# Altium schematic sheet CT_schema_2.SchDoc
size 276 x 169 mm
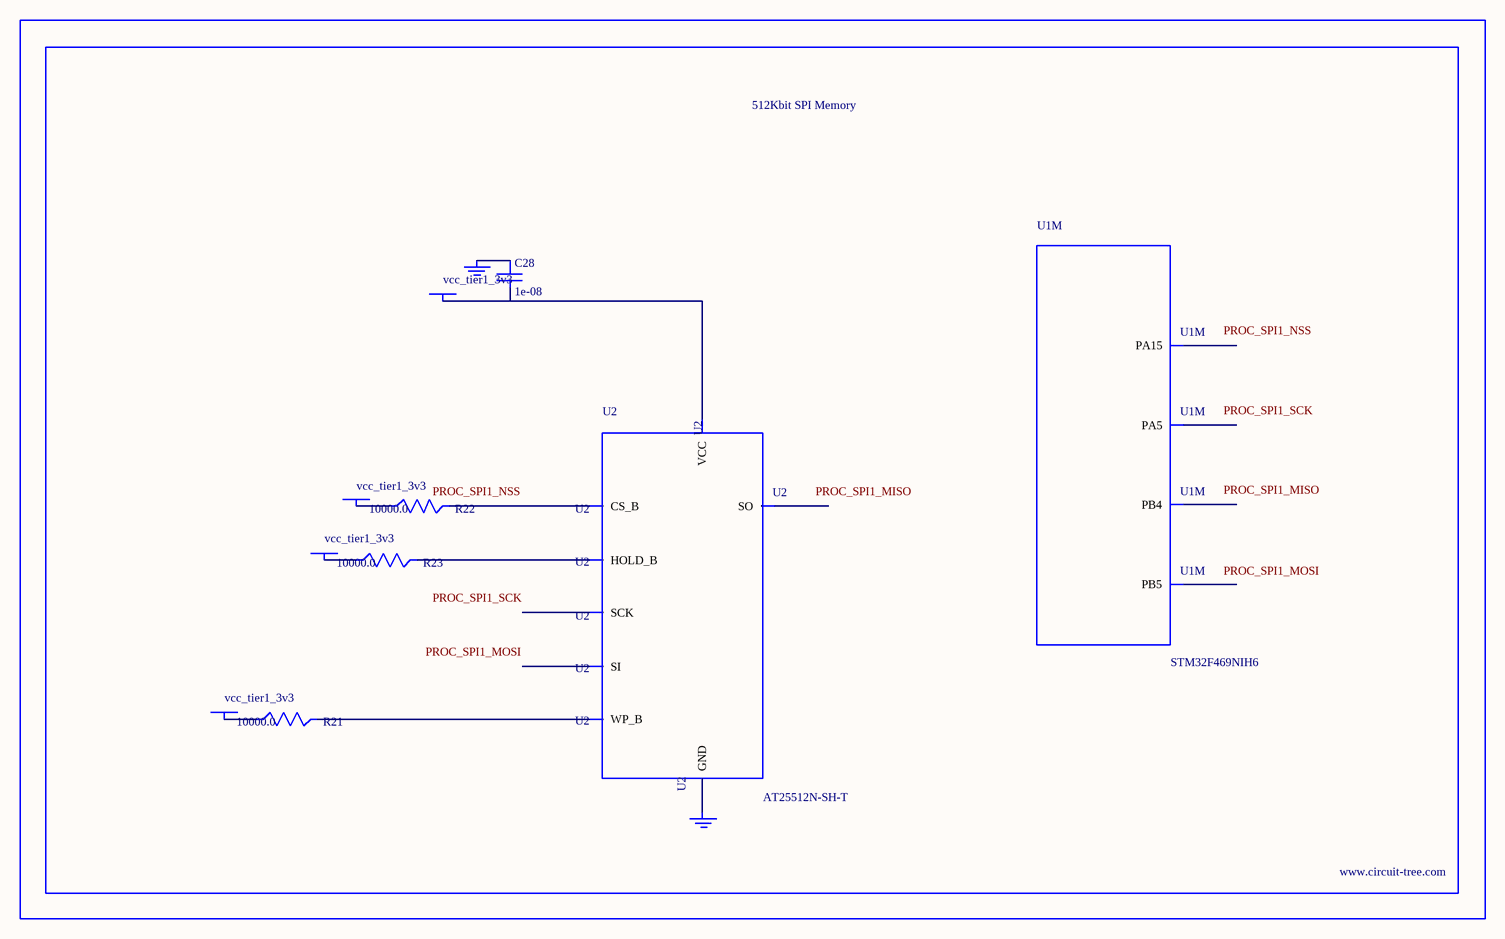
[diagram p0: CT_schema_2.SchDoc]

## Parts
BORDER1  (no value)
C28  1e-08  [C0402]
GND_INSTANCE_1_0  (no value)
GND_INSTANCE_1_1  (no value)
POWER_INSTANCE_1_0  vcc_tier1_3v3
POWER_INSTANCE_1_1  vcc_tier1_3v3
POWER_INSTANCE_1_2  vcc_tier1_3v3
POWER_INSTANCE_1_3  vcc_tier1_3v3
R21  10000.0  [R0603]
R22  10000.0  [R0603]
R23  10000.0  [R0603]
U1  STM32F469NIH6  [TFBGA216]  (part M of 17)
U2  AT25512N-SH-T  [SOIC-8]

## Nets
NetC28_1: C28.1 GND_INSTANCE_1_0.0(GND)
NetC28_2: C28.2 POWER_INSTANCE_1_3.0(PWR) U2.8(VCC)
NetGND_INSTANCE_1_1_0: GND_INSTANCE_1_1.0(GND) U2.4(GND)
NetPOWER_INSTANCE_1_0_0: POWER_INSTANCE_1_0.0(PWR) R22.1
NetPOWER_INSTANCE_1_1_0: POWER_INSTANCE_1_1.0(PWR) R21.1
NetPOWER_INSTANCE_1_2_0: POWER_INSTANCE_1_2.0(PWR) R23.1
NetR21_2: R21.2 U2.3(WP_B)
NetR22_2: R22.2 U2.1(CS_B)
NetR23_2: R23.2 U2.7(HOLD_B)

Not connected (* = marked no-connect by the designer): U1 A8(PB5) A9(PB4) A13(PA15) P4(PA5); U2 2(SO) 5(SI) 6(SCK)

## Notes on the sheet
- Labels drawn without touching a wire or pin: PROC_SPI1_MISO, PROC_SPI1_MOSI, PROC_SPI1_NSS, PROC_SPI1_SCK

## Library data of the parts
BORDER1 = BORDER_PAGE1
C28 = C0402C103K3RAC
GND_INSTANCE_1_0 GND_INSTANCE_1_1 = GND
POWER_INSTANCE_1_0-POWER_INSTANCE_1_3 = PWR
R21-R23 = RC0603JR-0710KL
